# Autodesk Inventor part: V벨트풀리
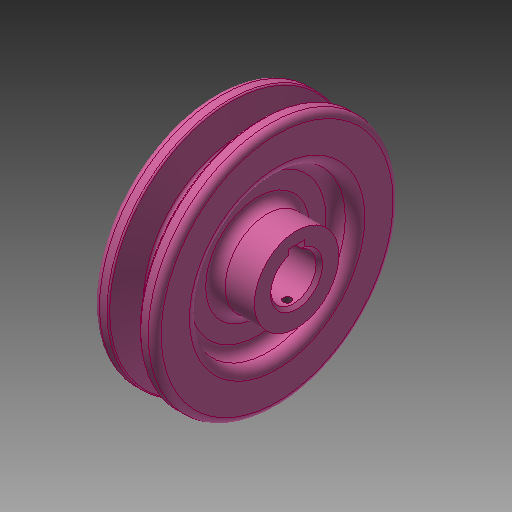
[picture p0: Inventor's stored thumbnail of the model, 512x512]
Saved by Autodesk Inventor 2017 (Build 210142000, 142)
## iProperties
Created: 2015-11
Part Number: V벨트풀리
Material: 강철, 탄소
Document SubType Name: Modeling
Designer: mduedu
Density: 1 g/cm^3
Appearance: 분홍색
Author: mduedu
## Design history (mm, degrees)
sketch "스케치1"
  geometry: L1 (-9.5, 0)-(9.5, 0); L2 (0, 0)-(0, 37.7); L3 (-4.825, 37.7)-(-9.5, 37.7); L4 (-9.5, 37.7)-(-9.5, 0); L5 (0, 28.7)-(-2.074, 28.7); L6 (-2.074, 28.7)-(-4.825, 37.7); L7 (4.825, 37.7)-(9.5, 37.7); L8 (9.5, 37.7)-(9.5, 0); L9 (0, 28.7)-(2.074, 28.7); L10 (2.074, 28.7)-(4.825, 37.7); L11 (-9.5, 35)-(9.5, 35); 3 further points
  constraints: 22 end point, 7 point on line, 4 perpendicular, 3 symmetric about line, 1 coincident, 1 horizontal, 1 horizontal alignment, 1 midpoint, 1 vertical
  dimensions: "d0" = 19 distance of L1.start L1.end; "d2" = 75.4 diameter of L2.end L1 (derived); "d3" = 34 deg angle of L10 L6; "d4" = 6.3 distance between parallel lines of L11 L9; "d5" = 2.7 distance between parallel lines of L7 L11; "d6" = 8 distance of point (4, 35) point (-4, 35); "d7" = 70 diameter of L11 L1
revolve "회전1" sketch "스케치1" stored, may be unused: angle "d8" = 90 deg
sketch "스케치2"
  geometry: C1 r 24 at (0, 0); C2 r 13 at (0, 0); 1 further point
  constraints: 2 centre point, 2 coincident
  dimensions: "d9" = 48 diameter of C1; "d10" = 26 diameter of C2
extrude "돌출1" cut sketch "스케치2" distance "d11" = 6; taper "d12" = 0 deg
extrude "돌출3" join sketch "스케치2" distance "d37" = 6; taper "d38" = 0 deg
fillet "모깎기1" dims "d13" = 3
fillet "모깎기2" dims "d14" = 3
fillet "모깎기3" dims "d15" = 1, "d16" = 0.5, "d17" = 2
hole "구멍1" diameter "d20" = 14; stored, may be unused: countersink angle "d24" = 90 deg, drill point angle "d26" = 118 deg; dims "d21" = 6, "d22" = 4, "d23" = 2, "d25" = 8, "d61" = 10, "d62" = 10
sketch "스케치3"
  geometry: L1 (-2.5, 0)-(2.5, 0); L2 (2.5, 0)-(2.5, 9.3); L3 (2.5, 9.3)-(-2.5, 9.3); L4 (-2.5, 9.3)-(-2.5, 0); 2 further points
  constraints: 8 end point, 2 parallel, 1 coincident, 1 horizontal, 1 midpoint, 1 perpendicular
  dimensions: "d27" = 5 distance of L2.end L3.end; "d29" = 9.3 distance of L3.end L1.start
extrude "돌출2" cut sketch "스케치3" stored distance "d30" = 6; taper "d31" = 0 deg
chamfer "모따기1" distance "d32" = 1; stored, may be unused: second distance "d33" = 2, angle "d34" = 45 deg
node "작업 평면1"
sketch "스케치4"
  geometry: L1 (19, -27)-(19, 27) reference; 2 further points
  constraints: 1 horizontal alignment
  dimensions: "d52" = 22 distance from line of L1 point (-3, 0)
hole "구멍2" sketch "스케치4" at (-3, 0) diameter "d42" = 2.459; stored, may be unused: countersink angle "d46" = 90 deg, drill point angle "d48" = 118 deg; dims "d43" = 6, "d44" = 4, "d45" = 2, "d47" = 8
chamfer "모따기3" distance "d58" = 1; stored, may be unused: second distance "d59" = 2, angle "d60" = 45 deg
node "솔리드1"
mirror "대칭1"
